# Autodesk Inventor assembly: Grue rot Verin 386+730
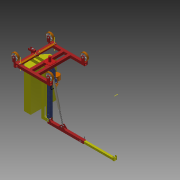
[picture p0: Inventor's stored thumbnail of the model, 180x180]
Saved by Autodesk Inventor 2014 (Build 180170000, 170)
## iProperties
Created: 2015-07
Part Number: Grue rot Verin 386+730
Document SubType Name: Assembly
Designer: OL
Author: OL
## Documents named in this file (29)
- D:\Lycée Larmand\Profs\SUJET BAC EDPI ETC\ELABORATION SUJET EDPI\Bourgeois RT 510\Modele Grue rotative\Grue rot Verin 386+730.iam
- D:\Lycée Larmand\Profs\SUJET BAC EDPI ETC\ELABORATION SUJET EDPI\Bourgeois RT 510\Modele Grue rotative\Cadre chariot.ipt
- D:\Lycée Larmand\Profs\SUJET BAC EDPI ETC\ELABORATION SUJET EDPI\Bourgeois RT 510\Modele Grue rotative\Axe.ipt
- D:\Lycée Larmand\Profs\SUJET BAC EDPI ETC\ELABORATION SUJET EDPI\Bourgeois RT 510\Modele Grue rotative\Poteau central.ipt
- D:\Lycée Larmand\Profs\SUJET BAC EDPI ETC\ELABORATION SUJET EDPI\Bourgeois RT 510\Modele Grue rotative\Potence pivot.ipt
- D:\Lycée Larmand\Profs\SUJET BAC EDPI ETC\ELABORATION SUJET EDPI\Bourgeois RT 510\Modele Grue rotative\Potence coulissante.ipt
- D:\Lycée Larmand\Profs\SUJET BAC EDPI ETC\ELABORATION SUJET EDPI\Bourgeois RT 510\Modele Grue rotative\Contrepoids.ipt
- D:\Lycée Larmand\Profs\SUJET BAC EDPI ETC\ELABORATION SUJET EDPI\Bourgeois RT 510\Modele Grue rotative\pompe\Pompe.ipt
- D:\Lycée Larmand\Profs\SUJET BAC EDPI ETC\ELABORATION SUJET EDPI\Bourgeois RT 510\Modele Grue rotative\Verin630-5-corps.ipt
- D:\Lycée Larmand\Profs\SUJET BAC EDPI ETC\ELABORATION SUJET EDPI\Bourgeois RT 510\Modele Grue rotative\Verin630-5-tige.ipt
- D:\Lycée Larmand\Profs\SUJET BAC EDPI ETC\ELABORATION SUJET EDPI\Bourgeois RT 510\Modele Grue rotative\Roue.ipt
- D:\Lycée Larmand\Profs\SUJET BAC EDPI ETC\ELABORATION SUJET EDPI\Bourgeois RT 510\Modele Grue rotative\Pivot de Direction.ipt
- D:\Lycée Larmand\Profs\SUJET BAC EDPI ETC\ELABORATION SUJET EDPI\Bourgeois RT 510\Modele Grue rotative\Palier de roue.ipt
- D:\Lycée Larmand\Profs\SUJET BAC EDPI ETC\ELABORATION SUJET EDPI\Bourgeois RT 510\Modele Grue rotative\Biellette.ipt
- D:\Lycée Larmand\Profs\SUJET BAC EDPI ETC\ELABORATION SUJET EDPI\Bourgeois RT 510\Modele Grue rotative\Vis H M10x20_02.ipt
- D:\Lycée Larmand\Profs\SUJET BAC EDPI ETC\ELABORATION SUJET EDPI\Bourgeois RT 510\Modele Grue rotative\Ecrou H M10x20_01.ipt
- D:\Lycée Larmand\Profs\SUJET BAC EDPI ETC\ELABORATION SUJET EDPI\Bourgeois RT 510\Modele Grue rotative\Axe D20.ipt
- D:\Lycée Larmand\Profs\SUJET BAC EDPI ETC\ELABORATION SUJET EDPI\Bourgeois RT 510\Modele Grue rotative\Goupille D20.ipt
- D:\Lycée Larmand\Profs\SUJET BAC EDPI ETC\ELABORATION SUJET EDPI\Bourgeois RT 510\Modele Grue rotative\Axe D20 L122.ipt
- D:\Lycée Larmand\Profs\SUJET BAC EDPI ETC\ELABORATION SUJET EDPI\Bourgeois RT 510\Modele Grue rotative\Rondelle d'appui D20.ipt
- D:\Lycée Larmand\Profs\SUJET BAC EDPI ETC\ELABORATION SUJET EDPI\Bourgeois RT 510\Modele Grue rotative\Axe D20 L96.ipt
- D:\Lycée Larmand\Profs\SUJET BAC EDPI ETC\ELABORATION SUJET EDPI\Bourgeois RT 510\Modele Grue rotative\Axe Roue D25 L116.ipt
- D:\Lycée Larmand\Profs\SUJET BAC EDPI ETC\ELABORATION SUJET EDPI\Bourgeois RT 510\Modele Grue rotative\Rondelle d'appui D25.ipt
- D:\Lycée Larmand\Profs\SUJET BAC EDPI ETC\ELABORATION SUJET EDPI\Bourgeois RT 510\Modele Grue rotative\Goupille D25.ipt
- D:\Lycée Larmand\Profs\SUJET BAC EDPI ETC\ELABORATION SUJET EDPI\Bourgeois RT 510\Modele Grue rotative\Butée manuelle.ipt
- D:\Lycée Larmand\Profs\SUJET BAC EDPI ETC\ELABORATION SUJET EDPI\Bourgeois RT 510\Modele Grue rotative\Goupille Cavalier.ipt
- D:\Lycée Larmand\Profs\SUJET BAC EDPI ETC\ELABORATION SUJET EDPI\Bourgeois RT 510\Modele Grue rotative\Bague d'arrêt D25.ipt
- D:\Lycée Larmand\Profs\SUJET BAC EDPI ETC\ELABORATION SUJET EDPI\Bourgeois RT 510\Modele Grue rotative\tuyau 1.ipt
- D:\Lycée Larmand\Profs\SUJET BAC EDPI ETC\ELABORATION SUJET EDPI\Bourgeois RT 510\Modele Grue rotative\tuyau 2.ipt
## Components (72 placed, 28 different names)
1. Cadre chariot:1 — Logement:1, Logement:9, Logement:10, Logement:12, Logement:13, Angle:1, Logement:37, Angle:12, Logement:38, Logement:39, Logement:42, Angle:15, Logement:43, Logement:44, Angle:16, Angle:17, Logement:54, Logement:74, Logement:75
2. Axe:1 — Logement:1, Logement:2
3. Poteau central:1 — Logement:2, Logement:3, Logement:4, Placage:3, Logement:5, Logement:6, Logement:7, Logement:21, Logement:22, Angle:3, Angle:6, Angle:7, Logement:27, Logement:28, Logement:57, Angle:20, Angle:22, Logement:58, Logement:60, Angle:24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
4. Potence pivot:1 — Logement:3, Placage:1, Placage:2, Placage:11, Logement:32, Angle:9, Logement:33, Logement:34, Logement:62, Angle:28
5. Potence coulissante:1 — Placage:1, Placage:2, Tangente:3
6. Contrepoids:1 — Logement:4, Placage:3, Angle:1, Angle:2, Logement:25, Logement:30, Logement:31
7. Pompe:1 — Logement:5, Logement:6, Logement:20, Logement:56, Angle:21, Angle:23, Logement:59, Logement:61, Angle:26, Angle:27, Logement:72
8. Verin630-5-corps:1 — Logement:7, Placage:4, Logement:73
9. Verin630-5-tige:1 — Placage:4, Placage:10
10. Roue:1 — Logement:9
11. Roue:2 — Logement:10
12. Pivot de Direction:1 — Logement:54, Logement:63, Angle:30, Angle:31, Placage:19, Placage:20
13. Palier de roue:1 — Logement:12, Logement:17, Logement:18, Placage:6, Angle:19, Logement:49, Logement:50, Logement:53, Placage:17, Angle:33
14. Palier de roue:2 — Logement:13, Logement:19, Angle:2, Placage:5, Logement:47, Angle:18, Logement:51, Logement:52, Logement:55, Placage:18, Angle:32
15. Biellette:1 — Logement:17, Placage:14, Logement:64, Logement:70
16. Biellette:2 — Logement:55, Placage:13, Logement:65, Logement:68
17. Roue:3 — Logement:18
18. Roue:4 — Logement:19
19. Vis H M10x20_02:1 — Logement:20, Angle:23
20. Ecrou H M10x20_01:1 — Logement:21, Angle:22
21. Axe D20:1 — Logement:22, Angle:3, Logement:23, Angle:4, Logement:24, Angle:5, Placage:24
22. Goupille D20:1 — Logement:24, Angle:5
23. Goupille D20:2 — Logement:23, Angle:4
24. Goupille D20:3 — Logement:26, Angle:7
25. Goupille D20:4 — Logement:29, Angle:8
26. Axe D20 L122:1 — Logement:25, Logement:26, Angle:6, Logement:29, Angle:8
27. Rondelle d'appui D20:1 — Logement:27
28. Rondelle d'appui D20:2 — Logement:28
29. Rondelle d'appui D20:3 — Logement:30
30. Rondelle d'appui D20:4 — Logement:31
31. Axe D20 L96:1 — Logement:32, Angle:9, Logement:35, Angle:10, Logement:36, Angle:11, Placage:23
32. Rondelle d'appui D20:5 — Logement:34
33. Rondelle d'appui D20:6 — Logement:33
34. Goupille D20:5 — Logement:35, Angle:10
35. Goupille D20:6 — Logement:36, Angle:11
36. Axe Roue D25 L116:1 — Logement:37, Angle:12, Angle:13, Angle:14
37. Rondelle d'appui D25:1 — Logement:38, Logement:41
38. Rondelle d'appui D25:2 — Logement:39, Logement:40
39. Goupille D25:1 — Logement:41, Angle:14
40. Goupille D25:2 — Logement:40, Angle:13
41. Axe Roue D25 L116:2 — Logement:42, Angle:15
42. Rondelle d'appui D25:3 — Logement:44, Logement:45
43. Rondelle d'appui D25:4 — Logement:43, Logement:46
44. Goupille D25:3 — Logement:45, Angle:16
45. Goupille D25:4 — Logement:46, Angle:17
46. Axe Roue D25 L116:3 — Logement:47, Angle:18
47. Axe Roue D25 L116:4 — Angle:19, Logement:53
48. Rondelle d'appui D25:5 — Logement:49
49. Rondelle d'appui D25:6 — Logement:50
50. Rondelle d'appui D25:7 — Logement:52
51. Rondelle d'appui D25:8 — Logement:51
52. Vis H M10x20_02:2 — Logement:56, Angle:21
53. Ecrou H M10x20_01:2 — Logement:57, Angle:20
54. Vis H M10x20_02:3 — Logement:59, Angle:26
55. Ecrou H M10x20_01:3 — Logement:58, Angle:24
56. Vis H M10x20_02:4 — Logement:61, Angle:27
57. Ecrou H M10x20_01:4 — Logement:60, Angle:25
58. Butée manuelle:1 — Logement:62, Angle:28, Placage:15, Affleurement:1, Angle:29, Tangente:3
59. Goupille Cavalier:1 — Placage:16, Affleurement:1, Angle:29
60. Bague d'arrêt D25:1 — Logement:63
61. Rondelle d'appui D20:7 — Logement:65, Logement:66, Placage:22
62. Rondelle d'appui D20:8 — Logement:64, Logement:67
63. Goupille D20:7 — Logement:66, Angle:30
64. Goupille D20:8 — Logement:67, Angle:31
65. Goupille D20:9 — Logement:69, Angle:32
66. Rondelle d'appui D20:9 — Logement:68, Logement:69
67. Rondelle d'appui D20:10 — Logement:70, Logement:71
68. Goupille D20:10 — Logement:71, Angle:33
69. tuyau 1:1 — Logement:72, Tangente:2
70. tuyau 2:1 — Logement:73, Tangente:2
71. Bague d'arrêt D25:2 — Logement:74
72. Bague d'arrêt D25:3 — Logement:75
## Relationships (124: Insert 69, Angle 33, Mate 19, Tangent 2, Flush 1)
- Logement:1 [Insert]: Cadre chariot:1 ↔ Axe:1
- Logement:2 [Insert]: Axe:1 ↔ Poteau central:1
- Logement:3 [Insert]: Poteau central:1 ↔ Potence pivot:1
- Placage:1 [Mate]: Potence pivot:1 ↔ Potence coulissante:1
- Placage:2 [Mate]: Potence pivot:1 ↔ Potence coulissante:1
- Logement:4 [Insert]: Poteau central:1 ↔ Contrepoids:1
- Placage:3 [Mate]: Poteau central:1 ↔ Contrepoids:1
- Logement:5 [Insert]: Poteau central:1 ↔ Pompe:1
- Logement:6 [Insert]: Poteau central:1 ↔ Pompe:1
- Logement:7 [Insert]: Poteau central:1 ↔ Verin630-5-corps:1
- Placage:4 [Mate]: Verin630-5-corps:1 ↔ Verin630-5-tige:1
- Logement:9 [Insert]: Cadre chariot:1 ↔ Roue:1
- Logement:10 [Insert]: Cadre chariot:1 ↔ Roue:2
- Logement:12 [Insert]: Cadre chariot:1 ↔ Palier de roue:1
- Logement:13 [Insert]: Cadre chariot:1 ↔ Palier de roue:2
- Logement:17 [Insert]: Palier de roue:1 ↔ Biellette:1
- Logement:18 [Insert]: Palier de roue:1 ↔ Roue:3
- Logement:19 [Insert]: Palier de roue:2 ↔ Roue:4
- Angle:1: Cadre chariot:1 ↔ Contrepoids:1
- Angle:2: Contrepoids:1 ↔ Palier de roue:2
- Placage:5 [Mate]: Palier de roue:2
- Placage:6 [Mate]: Palier de roue:1
- Logement:20 [Insert]: Pompe:1 ↔ Vis H M10x20_02:1
- Logement:21 [Insert]: Poteau central:1 ↔ Ecrou H M10x20_01:1
- Logement:22 [Insert]: Poteau central:1 ↔ Axe D20:1
- Angle:3: Poteau central:1 ↔ Axe D20:1
- Logement:23 [Insert]: Axe D20:1 ↔ Goupille D20:2
- Angle:4: Axe D20:1 ↔ Goupille D20:2
- Logement:24 [Insert]: Axe D20:1 ↔ Goupille D20:1
- Angle:5: Axe D20:1 ↔ Goupille D20:1
- Placage:10 [Mate]: Verin630-5-tige:1
- Placage:11 [Mate]: Potence pivot:1
- Logement:25 [Insert]: Contrepoids:1 ↔ Axe D20 L122:1
- Logement:26 [Insert]: Goupille D20:3 ↔ Axe D20 L122:1
- Angle:6: Poteau central:1 ↔ Axe D20 L122:1
- Angle:7: Poteau central:1 ↔ Goupille D20:3
- Logement:27 [Insert]: Poteau central:1 ↔ Rondelle d'appui D20:1
- Logement:28 [Insert]: Poteau central:1 ↔ Rondelle d'appui D20:2
- Logement:29 [Insert]: Goupille D20:4 ↔ Axe D20 L122:1
- Angle:8: Goupille D20:4 ↔ Axe D20 L122:1
- Logement:30 [Insert]: Contrepoids:1 ↔ Rondelle d'appui D20:3
- Logement:31 [Insert]: Contrepoids:1 ↔ Rondelle d'appui D20:4
- Logement:32 [Insert]: Potence pivot:1 ↔ Axe D20 L96:1
- Angle:9: Potence pivot:1 ↔ Axe D20 L96:1
- Logement:33 [Insert]: Potence pivot:1 ↔ Rondelle d'appui D20:6
- Logement:34 [Insert]: Potence pivot:1 ↔ Rondelle d'appui D20:5
- Logement:35 [Insert]: Axe D20 L96:1 ↔ Goupille D20:5
- Angle:10: Axe D20 L96:1 ↔ Goupille D20:5
- Logement:36 [Insert]: Axe D20 L96:1 ↔ Goupille D20:6
- Angle:11: Axe D20 L96:1 ↔ Goupille D20:6
- Logement:37 [Insert]: Cadre chariot:1 ↔ Axe Roue D25 L116:1
- Angle:12: Cadre chariot:1 ↔ Axe Roue D25 L116:1
- Logement:38 [Insert]: Cadre chariot:1 ↔ Rondelle d'appui D25:1
- Logement:39 [Insert]: Cadre chariot:1 ↔ Rondelle d'appui D25:2
- Logement:40 [Insert]: Rondelle d'appui D25:2 ↔ Goupille D25:2
- Angle:13: Axe Roue D25 L116:1 ↔ Goupille D25:2
- Logement:41 [Insert]: Rondelle d'appui D25:1 ↔ Goupille D25:1
- Angle:14: Axe Roue D25 L116:1 ↔ Goupille D25:1
- Logement:42 [Insert]: Cadre chariot:1 ↔ Axe Roue D25 L116:2
- Angle:15: Cadre chariot:1 ↔ Axe Roue D25 L116:2
- Logement:43 [Insert]: Cadre chariot:1 ↔ Rondelle d'appui D25:4
- Logement:44 [Insert]: Cadre chariot:1 ↔ Rondelle d'appui D25:3
- Logement:45 [Insert]: Rondelle d'appui D25:3 ↔ Goupille D25:3
- Angle:16: Cadre chariot:1 ↔ Goupille D25:3
- Logement:46 [Insert]: Rondelle d'appui D25:4 ↔ Goupille D25:4
- Angle:17: Cadre chariot:1 ↔ Goupille D25:4
- Logement:47 [Insert]: Palier de roue:2 ↔ Axe Roue D25 L116:3
- Angle:18: Palier de roue:2 ↔ Axe Roue D25 L116:3
- Angle:19: Palier de roue:1 ↔ Axe Roue D25 L116:4
- Logement:49 [Insert]: Palier de roue:1 ↔ Rondelle d'appui D25:5
- Logement:50 [Insert]: Palier de roue:1 ↔ Rondelle d'appui D25:6
- Logement:51 [Insert]: Palier de roue:2 ↔ Rondelle d'appui D25:8
- Logement:52 [Insert]: Palier de roue:2 ↔ Rondelle d'appui D25:7
- Logement:53 [Insert]: Palier de roue:1 ↔ Axe Roue D25 L116:4
- Logement:54 [Insert]: Cadre chariot:1 ↔ Pivot de Direction:1
- Logement:55 [Insert]: Palier de roue:2 ↔ Biellette:2
- Placage:13 [Mate]: Biellette:2
- Placage:14 [Mate]: Biellette:1
- Logement:56 [Insert]: Pompe:1 ↔ Vis H M10x20_02:2
- Logement:57 [Insert]: Poteau central:1 ↔ Ecrou H M10x20_01:2
- Angle:20: Poteau central:1 ↔ Ecrou H M10x20_01:2
- Angle:21: Pompe:1 ↔ Vis H M10x20_02:2
- Angle:22: Poteau central:1 ↔ Ecrou H M10x20_01:1
- Angle:23: Pompe:1 ↔ Vis H M10x20_02:1
- Logement:58 [Insert]: Poteau central:1 ↔ Ecrou H M10x20_01:3
- Logement:59 [Insert]: Pompe:1 ↔ Vis H M10x20_02:3
- Logement:60 [Insert]: Poteau central:1 ↔ Ecrou H M10x20_01:4
- Logement:61 [Insert]: Pompe:1 ↔ Vis H M10x20_02:4
- Angle:24: Poteau central:1 ↔ Ecrou H M10x20_01:3
- Angle:25: Poteau central:1 ↔ Ecrou H M10x20_01:4
- Angle:26: Pompe:1 ↔ Vis H M10x20_02:3
- Angle:27: Pompe:1 ↔ Vis H M10x20_02:4
- Logement:62 [Insert]: Potence pivot:1 ↔ Butée manuelle:1
- Angle:28: Potence pivot:1 ↔ Butée manuelle:1
- Placage:15 [Mate]: Butée manuelle:1
- Placage:16 [Mate]: Goupille Cavalier:1
- Affleurement:1 [Flush]: Butée manuelle:1 ↔ Goupille Cavalier:1
- Angle:29: Butée manuelle:1 ↔ Goupille Cavalier:1
- Logement:63 [Insert]: Pivot de Direction:1 ↔ Bague d'arrêt D25:1
- Logement:64 [Insert]: Biellette:1 ↔ Rondelle d'appui D20:8
- Logement:65 [Insert]: Biellette:2 ↔ Rondelle d'appui D20:7
- Logement:66 [Insert]: Rondelle d'appui D20:7 ↔ Goupille D20:7
- Angle:30: Pivot de Direction:1 ↔ Goupille D20:7
- Logement:67 [Insert]: Rondelle d'appui D20:8 ↔ Goupille D20:8
- Angle:31: Pivot de Direction:1 ↔ Goupille D20:8
- Placage:17 [Mate]: Palier de roue:1
- Placage:18 [Mate]: Palier de roue:2
- Placage:19 [Mate]: Pivot de Direction:1
- Placage:20 [Mate]: Pivot de Direction:1
- Placage:22 [Mate]: Rondelle d'appui D20:7
- Logement:68 [Insert]: Biellette:2 ↔ Rondelle d'appui D20:9
- Logement:69 [Insert]: Goupille D20:9 ↔ Rondelle d'appui D20:9
- Angle:32: Palier de roue:2 ↔ Goupille D20:9
- Logement:70 [Insert]: Biellette:1 ↔ Rondelle d'appui D20:10
- Logement:71 [Insert]: Rondelle d'appui D20:10 ↔ Goupille D20:10
- Angle:33: Palier de roue:1 ↔ Goupille D20:10
- Logement:72 [Insert]: Pompe:1 ↔ tuyau 1:1
- Logement:73 [Insert]: Verin630-5-corps:1 ↔ tuyau 2:1
- Tangente:2: tuyau 1:1 ↔ tuyau 2:1
- Logement:74 [Insert]: Cadre chariot:1 ↔ Bague d'arrêt D25:2
- Logement:75 [Insert]: Cadre chariot:1 ↔ Bague d'arrêt D25:3
- Placage:23 [Mate]: Axe D20 L96:1
- Placage:24 [Mate]: Axe D20:1
- Tangente:3: Potence coulissante:1 ↔ Butée manuelle:1
